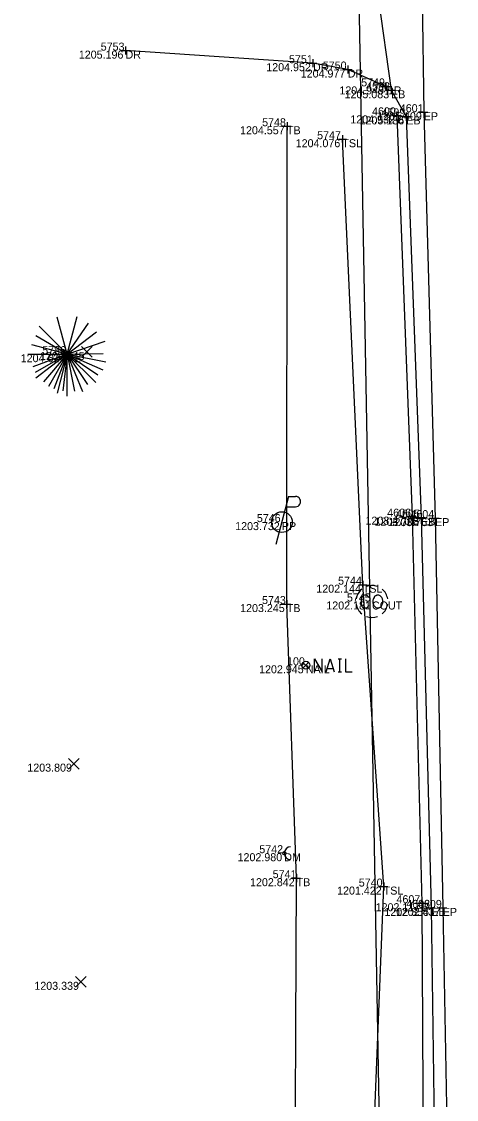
# Model space of a CAD drawing. Extents: x 2044996 to 2050343, y 455232 to 458054.
# Drawn here: x 2047578.2 to 2047632.7, y 456516 to 456650.7 of the extents above; entities that cross this region are included whole.
import ezdxf

# ---------------------------------------------------------------- set-up
doc = ezdxf.new("R2010")
doc.units = 0
for name, color, linetype in [('DR_X_Cells', 7, 'Continuous'), ('DR_X_Storm_Sewer', 7, 'Continuous'), ('DT_X_Contour_Major', 7, 'Continuous'), ('DT_X_Contour_Minor', 7, 'Continuous'), ('DT_X_Contour_Text', 7, 'Continuous'), ('DT_X_Island', 7, 'Continuous'), ('DT_X_Spot_Elev', 7, 'Continuous'), ('DT_X_Triangles', 7, 'Continuous'), ('DT_X_Void', 7, 'Continuous'), ('PV_X_Driveway', 7, 'Continuous'), ('PV_X_EOP', 7, 'Continuous'), ('PV_X_Shoulder_Aggregate', 7, 'Continuous'), ('SV_X_Break_Lines', 7, 'Continuous'), ('SV_X_Toe_of_Slope', 7, 'Continuous'), ('SV_X_Top_of_Bank', 7, 'Continuous'), ('UT_X_Electric_Cells', 7, 'Continuous'), ('VG_X_Cells', 7, 'Continuous')]:
    doc.layers.add(name, color=color, linetype=linetype)

msp = doc.modelspace()

# ---------------------------------------------------------------- linework, layer by layer
at = {"layer": 'DR_X_Cells'}
msp.add_line((2047622.08, 456578.21), (2047622.08, 456578.21), dxfattribs=at)
for points in [[(2047621.67, 456578.69), (2047621.61, 456578.83), (2047621.54, 456578.91), (2047621.48, 456578.96), (2047621.43, 456578.98), (2047621.29, 456579.01), (2047621.15, 456579.01), (2047620.98, 456578.96), (2047620.88, 456578.88), (2047620.82, 456578.82), (2047620.77, 456578.73), (2047620.74, 456578.59), (2047620.72, 456578.34), (2047620.72, 456578.15), (2047620.72, 456578.02), (2047620.74, 456577.91), (2047620.77, 456577.71), (2047620.79, 456577.67), (2047620.84, 456577.58), (2047620.89, 456577.52), (2047620.98, 456577.46), (2047621.05, 456577.43), (2047621.15, 456577.41), (2047621.27, 456577.41), (2047621.38, 456577.42), (2047621.42, 456577.43), (2047621.47, 456577.46), (2047621.52, 456577.51), (2047621.58, 456577.57), (2047621.63, 456577.65), (2047621.67, 456577.71)], [(2047622.69, 456578.99), (2047622.65, 456578.98), (2047622.61, 456578.97), (2047622.55, 456578.93), (2047622.51, 456578.91), (2047622.45, 456578.86), (2047622.4, 456578.81), (2047622.37, 456578.78), (2047622.34, 456578.73), (2047622.27, 456578.6), (2047622.22, 456578.48), (2047622.2, 456578.36), (2047622.19, 456578.2), (2047622.2, 456578.02), (2047622.24, 456577.9), (2047622.27, 456577.8), (2047622.3, 456577.75), (2047622.34, 456577.68), (2047622.39, 456577.62), (2047622.42, 456577.58), (2047622.46, 456577.55), (2047622.51, 456577.51), (2047622.58, 456577.47), (2047622.69, 456577.42), (2047622.75, 456577.41), (2047622.88, 456577.41), (2047622.93, 456577.42), (2047622.98, 456577.43), (2047623.04, 456577.46), (2047623.11, 456577.5), (2047623.14, 456577.52), (2047623.18, 456577.55), (2047623.22, 456577.58), (2047623.26, 456577.63), (2047623.28, 456577.67), (2047623.31, 456577.71), (2047623.33, 456577.75), (2047623.37, 456577.82), (2047623.41, 456577.91), (2047623.43, 456578.01), (2047623.45, 456578.1), (2047623.45, 456578.11), (2047623.45, 456578.2), (2047623.45, 456578.28), (2047623.43, 456578.38), (2047623.41, 456578.48), (2047623.38, 456578.55), (2047623.34, 456578.64), (2047623.31, 456578.72), (2047623.24, 456578.79), (2047623.19, 456578.84), (2047623.14, 456578.89), (2047623.09, 456578.93), (2047623.02, 456578.97), (2047622.94, 456578.99), (2047622.87, 456579.01), (2047622.78, 456579.01), (2047622.69, 456578.99)]]:
    msp.add_lwpolyline(points, dxfattribs=at)
for start, end in [(130.0806, 170.0721), (70.0577, 110.1061), (10.0169, 50.0392), (190.0169, 230.0392), (310.0114, 350.0264), (250.0577, 290.0473)]:
    msp.add_arc((2047622.08, 456578.21), 2, start, end, dxfattribs=at)
at = {"layer": 'DR_X_Storm_Sewer'}
msp.add_line((2047618.84, 456740.61), (2047628.62, 456202.21), dxfattribs=at)
at = {"layer": 'DT_X_Contour_Major'}
for p, q in [((2047613.45, 456570.59), (2047614.16, 456569.89)), ((2047613.45, 456569.89), (2047614.16, 456570.59))]:
    msp.add_line(p, q, dxfattribs=at)
for points in [[(2047614.9, 456569.43), (2047614.9, 456571.03), (2047615.84, 456569.43), (2047615.84, 456571.03)], [(2047616.35, 456569.43), (2047616.85, 456571.03), (2047617.34, 456569.43)], [(2047617.84, 456571.03), (2047618.25, 456571.03)], [(2047618.05, 456569.43), (2047618.05, 456571.03)], [(2047618.75, 456571.03), (2047618.75, 456569.43), (2047619.62, 456569.43)], [(2047617.22, 456569.81), (2047616.47, 456569.81)], [(2047617.84, 456569.43), (2047618.25, 456569.43)]]:
    msp.add_lwpolyline(points, dxfattribs=at)
msp.add_circle((2047613.81, 456570.24), 0.5, dxfattribs=at)
at = {"layer": 'DT_X_Island'}
msp.add_circle((2047611.11, 456546.76), 0.2, dxfattribs=at)
msp.add_arc((2047611.91, 456546.76), 0.8, 90, 270, dxfattribs=at)
at = {"layer": 'DT_X_Spot_Elev'}
for p, q in [((2047585.74, 456608.72), (2047587.07, 456610.06)), ((2047585.74, 456610.06), (2047587.07, 456608.72)), ((2047584.13, 456557.28), (2047585.46, 456558.61)), ((2047584.13, 456558.61), (2047585.46, 456557.28)), ((2047585, 456530.02), (2047586.34, 456531.35)), ((2047585, 456531.35), (2047586.34, 456530.02))]:
    msp.add_line(p, q, dxfattribs=at)
at = {"layer": 'DT_X_Void'}
for p, q in [((2047590.75, 456647.04), (2047591.75, 456647.04)), ((2047591.25, 456647.54), (2047591.25, 456646.54)), ((2047591.25, 456647.04), (2047591.25, 456647.04)), ((2047614.2, 456645.47), (2047615.2, 456645.47)), ((2047614.7, 456645.97), (2047614.7, 456644.97)), ((2047614.7, 456645.47), (2047614.7, 456645.47)), ((2047618.55, 456644.68), (2047619.55, 456644.68)), ((2047619.05, 456645.18), (2047619.05, 456644.18)), ((2047619.05, 456644.68), (2047619.05, 456644.68)), ((2047623.83, 456643.07), (2047623.83, 456642.07)), ((2047623.33, 456642.57), (2047624.33, 456642.57)), ((2047623.83, 456642.57), (2047623.83, 456642.57)), ((2047623.97, 456642.09), (2047624.97, 456642.09)), ((2047624.47, 456642.59), (2047624.47, 456641.59)), ((2047624.47, 456642.09), (2047624.47, 456642.09)), ((2047624.71, 456638.95), (2047625.71, 456638.95)), ((2047625.21, 456639.45), (2047625.21, 456638.45)), ((2047625.21, 456638.95), (2047625.21, 456638.95)), ((2047625.87, 456638.82), (2047626.87, 456638.82)), ((2047626.37, 456639.32), (2047626.37, 456638.32)), ((2047626.37, 456638.82), (2047626.37, 456638.82)), ((2047628.06, 456639.34), (2047629.06, 456639.34)), ((2047628.56, 456639.84), (2047628.56, 456638.84)), ((2047628.56, 456639.34), (2047628.56, 456639.34)), ((2047610.96, 456637.59), (2047611.96, 456637.59)), ((2047611.46, 456638.09), (2047611.46, 456637.09)), ((2047611.46, 456637.59), (2047611.46, 456637.59)), ((2047617.88, 456635.97), (2047618.88, 456635.97)), ((2047618.38, 456636.47), (2047618.38, 456635.47)), ((2047618.38, 456635.97), (2047618.38, 456635.97)), ((2047626.61, 456588.81), (2047627.61, 456588.81)), ((2047627.11, 456589.31), (2047627.11, 456588.31)), ((2047627.11, 456588.81), (2047627.11, 456588.81)), ((2047628.22, 456589.19), (2047628.22, 456588.19)), ((2047629.98, 456589.13), (2047629.98, 456588.13)), ((2047627.72, 456588.69), (2047628.72, 456588.69)), ((2047628.22, 456588.69), (2047628.22, 456588.69)), ((2047629.48, 456588.63), (2047630.48, 456588.63)), ((2047629.98, 456588.63), (2047629.98, 456588.63)), ((2047620.93, 456580.81), (2047620.93, 456579.81)), ((2047620.43, 456580.31), (2047621.43, 456580.31)), ((2047620.93, 456580.31), (2047620.93, 456580.31)), ((2047611.43, 456578.39), (2047611.43, 456577.39)), ((2047610.93, 456577.89), (2047611.93, 456577.89)), ((2047611.43, 456577.89), (2047611.43, 456577.89)), ((2047612.16, 456543.64), (2047613.16, 456543.64)), ((2047612.66, 456544.14), (2047612.66, 456543.14)), ((2047612.66, 456543.64), (2047612.66, 456543.64)), ((2047623.55, 456543.09), (2047623.55, 456542.09)), ((2047623.05, 456542.59), (2047624.05, 456542.59)), ((2047623.55, 456542.59), (2047623.55, 456542.59)), ((2047627.82, 456540.51), (2047628.82, 456540.51)), ((2047628.32, 456541.01), (2047628.32, 456540.01)), ((2047628.32, 456540.51), (2047628.32, 456540.51)), ((2047629.49, 456540.43), (2047629.49, 456539.43)), ((2047630.94, 456540.42), (2047630.94, 456539.42)), ((2047628.99, 456539.93), (2047629.99, 456539.93)), ((2047629.49, 456539.93), (2047629.49, 456539.93)), ((2047630.44, 456539.92), (2047631.44, 456539.92)), ((2047630.94, 456539.92), (2047630.94, 456539.92))]:
    msp.add_line(p, q, dxfattribs=at)
at = {"layer": 'PV_X_Driveway'}
msp.add_lwpolyline([(2047623.83, 456642.57), (2047619.05, 456644.68), (2047614.7, 456645.47), (2047591.25, 456647.04)], dxfattribs=at)
at = {"layer": 'PV_X_EOP'}
for p, q in [((2047627.89, 456685.01), (2047628.56, 456639.34)), ((2047628.56, 456639.34), (2047629.98, 456588.63)), ((2047629.98, 456588.63), (2047630.94, 456539.92)), ((2047630.94, 456539.92), (2047631.78, 456493.67))]:
    msp.add_line(p, q, dxfattribs=at)
at = {"layer": 'PV_X_Shoulder_Aggregate'}
for p, q in [((2047622.32, 456657.41), (2047624.47, 456642.09)), ((2047624.47, 456642.09), (2047626.37, 456638.82)), ((2047626.37, 456638.82), (2047628.22, 456588.69)), ((2047628.22, 456588.69), (2047629.49, 456539.93)), ((2047629.49, 456539.93), (2047630.15, 456493.85))]:
    msp.add_line(p, q, dxfattribs=at)
at = {"layer": 'SV_X_Break_Lines'}
msp.add_lwpolyline([(2047625.21, 456638.95), (2047627.11, 456588.81), (2047628.32, 456540.51), (2047628.58, 456493.59), (2047629.46, 456445.22), (2047630.66, 456399.52), (2047631.97, 456357.07), (2047632.12, 456312.85), (2047632.56, 456284.1)], dxfattribs=at)
at = {"layer": 'SV_X_Toe_of_Slope'}
msp.add_lwpolyline([(2047627.42, 456261.1), (2047625.53, 456304.38), (2047624.71, 456355.98), (2047623.95, 456397.69), (2047623.34, 456452.18), (2047621.68, 456495.65), (2047623.55, 456542.59), (2047620.93, 456580.31), (2047618.38, 456635.97)], dxfattribs=at)
at = {"layer": 'SV_X_Top_of_Bank'}
msp.add_lwpolyline([(2047619.16, 456260.18), (2047618.27, 456307.13), (2047618.14, 456352.85), (2047617.01, 456400.11), (2047615.66, 456448.08), (2047612.43, 456496.09), (2047612.66, 456543.64), (2047611.43, 456577.89), (2047611.46, 456637.59)], dxfattribs=at)
at = {"layer": 'UT_X_Electric_Cells'}
for p, q in [((2047611.66, 456591.33), (2047610.06, 456585.33)), ((2047611.66, 456591.33), (2047612.51, 456591.33)), ((2047611.32, 456590.05), (2047612.51, 456590.05))]:
    msp.add_line(p, q, dxfattribs=at)
msp.add_circle((2047610.81, 456588.13), 1.3, dxfattribs=at)
msp.add_arc((2047612.52, 456590.69), 0.638, 268.8767, 91.1233, dxfattribs=at)
at = {"layer": 'VG_X_Cells'}
for p, q in [((2047583.95, 456609.11), (2047582.72, 456613.72)), ((2047583.95, 456609.11), (2047585.21, 456613.81)), ((2047583.95, 456609.11), (2047580.46, 456612.6)), ((2047583.95, 456609.11), (2047586.61, 456612.99)), ((2047583.95, 456609.11), (2047587.61, 456611.91)), ((2047583.95, 456609.11), (2047580.04, 456611.41)), ((2047583.95, 456609.11), (2047588.69, 456610.72)), ((2047579.02, 456609.11), (2047583.95, 456609.11)), ((2047583.95, 456609.11), (2047579.54, 456610.29)), ((2047583.95, 456609.11), (2047579.66, 456607.55)), ((2047583.95, 456609.11), (2047579.97, 456606.83)), ((2047583.95, 456609.11), (2047580.04, 456606.11)), ((2047583.95, 456609.11), (2047581.01, 456605.64)), ((2047583.95, 456609.11), (2047581.63, 456605.09)), ((2047583.95, 456609.11), (2047582.29, 456604.77)), ((2047583.95, 456609.11), (2047582.69, 456604.25)), ((2047583.95, 456609.11), (2047583.41, 456604.52)), ((2047583.95, 456609.11), (2047588.46, 456609.2)), ((2047583.95, 456603.87), (2047583.95, 456609.11)), ((2047583.95, 456609.11), (2047584.87, 456604.47)), ((2047583.95, 456609.11), (2047585.88, 456604.44)), ((2047583.95, 456609.11), (2047586.49, 456605.32)), ((2047583.95, 456609.11), (2047587.54, 456605.59)), ((2047583.95, 456609.11), (2047587.77, 456606.55)), ((2047583.95, 456609.11), (2047588.42, 456607.17)), ((2047583.95, 456609.11), (2047588.78, 456608.15))]:
    msp.add_line(p, q, dxfattribs=at)

# ---------------------------------------------------------------- texts
at = {"layer": 'DT_X_Contour_Minor'}
for s, p in [('1205.196', (2047585.41, 456646.04)), ('1204.952', (2047608.86, 456644.47)), ('1204.977', (2047613.17, 456643.68)), ('1204.949', (2047618.01, 456641.57)), ('1205.083', (2047618.65, 456641.09)), ('1204.932', (2047619.37, 456637.95)), ('1205.186', (2047620.53, 456637.82)), ('1205.409', (2047622.74, 456638.34)), ('1204.557', (2047605.58, 456636.59)), ('1204.076', (2047612.54, 456634.97)), ('1204.624', (2047578.14, 456608.11)), ('1204.545', (2047580.56, 456608.39)), ('1203.470', (2047621.27, 456587.81)), ('1203.732', (2047604.97, 456587.13)), ('1203.708', (2047622.39, 456587.69)), ('1203.763', (2047624.15, 456587.63)), ('1202.144', (2047615.12, 456579.31)), ('1202.181', (2047616.37, 456577.21)), ('1203.245', (2047605.59, 456576.89)), ('1202.945', (2047607.96, 456569.24)), ('1203.809', (2047578.97, 456556.95)), ('1202.980', (2047605.27, 456545.76)), ('1202.842', (2047606.83, 456542.64)), ('1201.422', (2047617.72, 456541.59)), ('1202.117', (2047622.54, 456539.51)), ('1202.355', (2047623.64, 456538.93)), ('1202.437', (2047625.06, 456538.92)), ('1203.339', (2047579.85, 456529.69))]:
    msp.add_text(s, height=1, dxfattribs=at).set_placement(p)
at = {"layer": 'DT_X_Contour_Text'}
for s, p in [('DR', (2047591.25, 456646.04)), ('DR', (2047614.7, 456644.47)), ('DR', (2047619.05, 456643.68)), ('DR', (2047623.83, 456641.57)), ('EB', (2047624.47, 456641.09)), ('B', (2047625.21, 456637.95)), ('EB', (2047626.37, 456637.82)), ('EP', (2047628.56, 456638.34)), ('TB', (2047611.46, 456636.59)), ('TSL', (2047618.38, 456634.97)), ('TE', (2047583.95, 456608.11)), ('B', (2047627.11, 456587.81)), ('PP', (2047610.81, 456587.13)), ('EB', (2047628.22, 456587.69)), ('EP', (2047629.98, 456587.63)), ('TSL', (2047620.93, 456579.31)), ('COUT', (2047622.08, 456577.21)), ('TB', (2047611.43, 456576.89)), ('NAIL', (2047613.81, 456569.24)), ('DM', (2047611.11, 456545.76)), ('TB', (2047612.66, 456542.64)), ('TSL', (2047623.55, 456541.59)), ('B', (2047628.32, 456539.51)), ('EB', (2047629.49, 456538.93)), ('EP', (2047630.94, 456538.92))]:
    msp.add_text(s, height=1, dxfattribs=at).set_placement(p)
at = {"layer": 'DT_X_Triangles'}
for s, p in [('5753', (2047588.15, 456647.04)), ('5751', (2047611.7, 456645.47)), ('5750', (2047615.93, 456644.68)), ('5749', (2047620.73, 456642.57)), ('4598', (2047621.35, 456642.09)), ('4600', (2047622.09, 456638.95)), ('4601', (2047625.56, 456639.34)), ('5748', (2047608.34, 456637.59)), ('4599', (2047623.28, 456638.82)), ('5747', (2047615.22, 456635.97)), ('5786', (2047580.83, 456609.11)), ('5746', (2047607.68, 456588.13)), ('4606', (2047623.99, 456588.81)), ('4605', (2047625.09, 456588.69)), ('4604', (2047626.89, 456588.63)), ('5744', (2047617.84, 456580.31)), ('5743', (2047608.33, 456577.89)), ('5745', (2047618.95, 456578.21)), ('100', (2047611.46, 456570.24)), ('5742', (2047607.99, 456546.76)), ('5741', (2047609.66, 456543.64)), ('5740', (2047620.43, 456542.59)), ('4607', (2047625.15, 456540.51)), ('4608', (2047626.37, 456539.93)), ('4609', (2047627.84, 456539.92))]:
    msp.add_text(s, height=1, dxfattribs=at).set_placement(p)

doc.saveas('drawing.dxf')
